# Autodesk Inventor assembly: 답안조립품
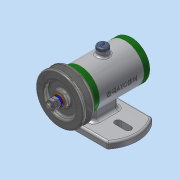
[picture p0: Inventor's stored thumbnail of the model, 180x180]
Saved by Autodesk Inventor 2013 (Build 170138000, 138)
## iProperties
Created: 2017-12
Part Number: 답안조립품
Document SubType Name: Assembly
Designer: dgall
Author: dgall
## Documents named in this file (14)
- C:\Users\dgall\Desktop\471207V1031\답안조립품.iam
- C:\Users\dgall\Desktop\471207V1031\본체.ipt
- C:\Users\dgall\Desktop\471207V1031\V벨트풀리.ipt
- C:\Users\dgall\Desktop\471207V1031\축.ipt
- C:\Users\dgall\Desktop\471207V1031\키 3 x 3 x 12.ipt
- C:\Users\dgall\Desktop\471207V1031\너트 M 8.ipt
- C:\Users\dgall\Desktop\471207V1031\스프링와셔 8.ipt
- C:\Users\dgall\Desktop\471207V1031\와셔 8x17.ipt
- C:\Users\dgall\Desktop\471207V1031\베어링 15 x 32 x 9.ipt
- C:\Users\dgall\Desktop\471207V1031\앞커버.ipt
- C:\Users\dgall\Desktop\471207V1031\오일 실 15 25 7.ipt
- C:\Users\dgall\Desktop\471207V1031\뒤커버.ipt
- C:\Users\dgall\Desktop\471207V1031\볼트 M4 x 12.ipt
- C:\Users\dgall\Desktop\471207V1031\고무캡.ipt
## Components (2 placed, 2 different names)
1. V벨트풀리:1 — 각도:2
2. 고무캡:1
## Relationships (1: Angle 1)
- 각도:2 [Angle]: V벨트풀리:1
